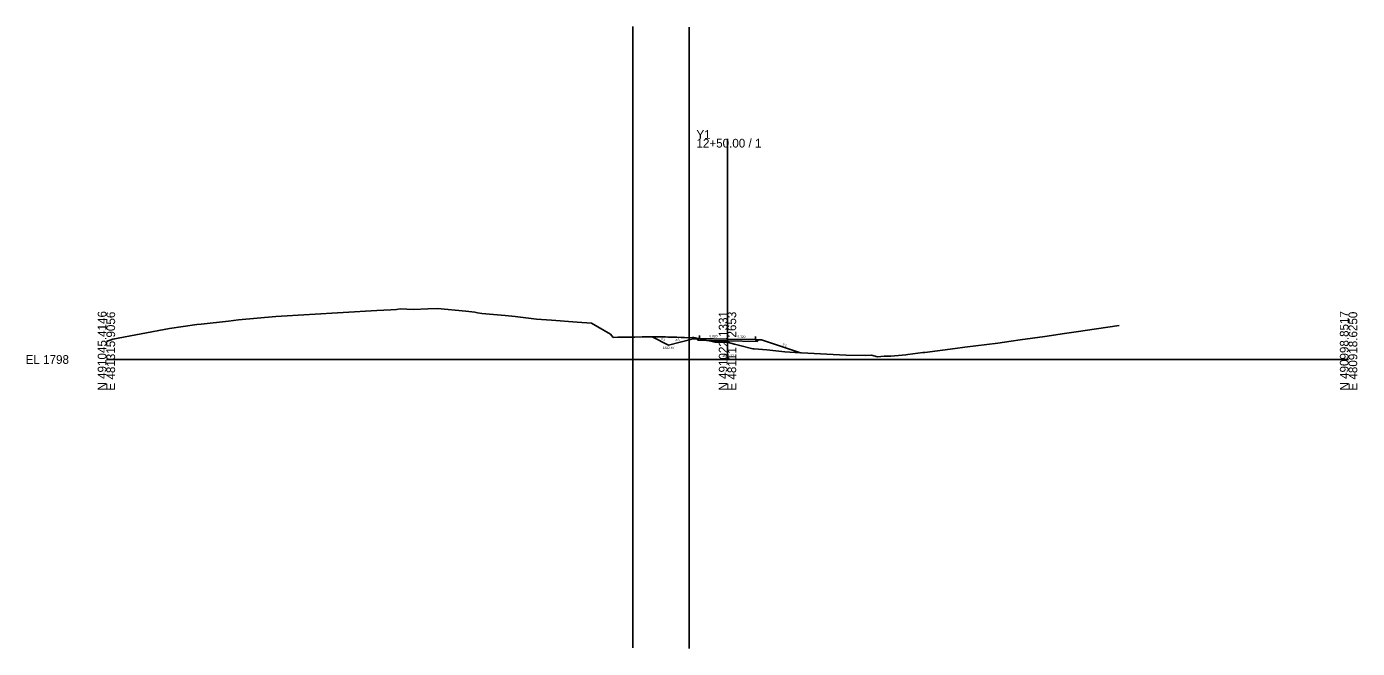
# Model space of a CAD drawing. Extents: x -26 to 403, y -10 to 6561.
# Drawn here: x -25.7 to 402.8, y 2407 to 2607.2 of the extents above; entities that cross this region are included whole.
import ezdxf

# ---------------------------------------------------------------- set-up
doc = ezdxf.new("R2010")
doc.units = 0
for name, color, linetype in [('Exist Cross Section Cell', 7, 'Continuous'), ('Exist XS Center Line Elevation Label', 7, 'Continuous'), ('Exist XS Ground Line', 7, 'Continuous'), ('Prop Road Sect_ Boring - Header (ID Tx)', 7, 'Continuous'), ('Prop Road Sect_ Material - Tx (Composite Desc)', 7, 'Continuous'), ('Prop XS Ditch Slope Text', 7, 'Continuous'), ('Prop XS Ditch Standard Text', 7, 'Continuous'), ('Prop XS EOT Tick Mark', 7, 'Continuous'), ('Prop XS Finish Grade', 7, 'Continuous'), ('Prop XS Finish Grade Earthwork', 7, 'Continuous'), ('Prop XS Finish Grade Pavement', 7, 'Continuous'), ('Prop XS Pvmt Edge Slope', 7, 'Continuous'), ('Prop XS SE Text', 7, 'Continuous'), ('Prop XS Side Slope Text', 7, 'Continuous'), ('Prop XS Subgrade Earthwork', 7, 'Continuous'), ('Scratch_Level_1', 7, 'Continuous')]:
    doc.layers.add(name, color=color, linetype=linetype)

msp = doc.modelspace()

# ---------------------------------------------------------------- linework, layer by layer
at = {"layer": 'Exist Cross Section Cell'}
for p, q in [((200, 2500), (200, 2571.04)), ((0, 2500), (200, 2500)), ((200, 2500), (400, 2500))]:
    msp.add_line(p, q, dxfattribs=at)
at = {"layer": 'Exist XS Ground Line'}
msp.add_lwpolyline([(0, 2505.84), (2.02, 2506.57), (20.27, 2509.97), (29.12, 2511.22), (30.53, 2511.41), (39.34, 2512.36), (42.55, 2512.72), (54.59, 2513.85), (87.06, 2515.79), (91.56, 2516.04), (93.38, 2516.14), (94.55, 2516.29), (98.94, 2516.1), (103.51, 2516.32), (106.6, 2516.41), (115.75, 2515.57), (118.65, 2515.21), (119.53, 2515.04), (120.93, 2514.85), (128.44, 2514.13), (131.66, 2513.85), (138.55, 2512.98), (143.38, 2512.66), (151.62, 2512.06), (156.21, 2511.71), (162.28, 2508.11), (163.23, 2507.13), (164.7, 2507.18), (165.48, 2507.18), (168.52, 2507.16), (169.54, 2507.16), (170.2, 2507.19), (172.5, 2507.26), (174.08, 2507.28), (175.15, 2507.28), (177.74, 2507.28), (178.75, 2507.28), (179.54, 2507.26), (180.04, 2507.25), (180.84, 2507.23), (182.54, 2507.2), (183.68, 2507.16), (185.05, 2507.12), (186.13, 2507.08), (187.66, 2507.01), (187.86, 2507.03), (188.71, 2507.04), (189.13, 2507.04), (193.16, 2506.19), (194.16, 2505.98), (194.68, 2505.88), (195.94, 2505.59), (198.56, 2505.57), (199.95, 2505.59), (202.22, 2504.92), (203.93, 2504.47), (208.19, 2503.49), (208.55, 2503.47), (212.63, 2503.13), (218.5, 2502.44), (220.07, 2502.39), (221.81, 2502.23), (236.05, 2501.52), (238.26, 2501.44), (244.53, 2501.33), (246.34, 2501.37), (248.35, 2500.81), (250.46, 2501.07), (252.62, 2501.12), (256.27, 2501.36), (257.38, 2501.52), (258.05, 2501.63), (262.89, 2502.22), (263.5, 2502.25), (273.34, 2503.57), (276.48, 2503.96), (287.1, 2505.31), (291.33, 2505.86), (294.26, 2506.3), (302.24, 2507.44), (308.55, 2508.33), (312.31, 2508.91), (318.81, 2509.88), (326.11, 2510.95)], dxfattribs=at)
at = {"layer": 'Prop Road Sect_ Boring - Header (ID Tx)'}
for points in [[(190.47, 2506.22), (189.98, 2506.71), (191, 2506.75)], [(210.06, 2506.35), (209.55, 2505.84), (209, 2506.39)]]:
    msp.add_lwpolyline(points, close=True, dxfattribs=at)
at = {"layer": 'Prop Road Sect_ Material - Tx (Composite Desc)'}
for points in [[(189, 2506.67), (189.98, 2506.71), (190.47, 2506.22), (193.28, 2506.16), (193.16, 2506.19), (189.13, 2507.04), (188.71, 2507.04), (187.86, 2507.03), (187.66, 2507.01), (186.13, 2507.08), (185.05, 2507.12), (183.68, 2507.16), (182.54, 2507.2), (180.84, 2507.23), (180.04, 2507.25), (179.54, 2507.26), (178.75, 2507.28), (177.74, 2507.28), (175.78, 2507.28), (181, 2504.67)], [(199.99, 2506.03), (209.55, 2505.84), (210.06, 2506.35), (211, 2506.31), (223.5, 2502.14), (221.81, 2502.23), (220.07, 2502.39), (218.5, 2502.44), (212.63, 2503.13), (208.55, 2503.47), (208.19, 2503.49), (203.93, 2504.47), (202.22, 2504.92), (199.95, 2505.59), (198.56, 2505.57), (195.94, 2505.59), (194.68, 2505.88), (194.16, 2505.98), (193.28, 2506.16)]]:
    msp.add_lwpolyline(points, close=True, dxfattribs=at)
at = {"layer": 'Prop XS EOT Tick Mark'}
for p, q in [((191, 2506.75), (191, 2507.75)), ((209, 2506.39), (209, 2507.39))]:
    msp.add_line(p, q, dxfattribs=at)
at = {"layer": 'Prop XS Finish Grade'}
for p, q in [((191, 2506.75), (189.98, 2506.71)), ((209, 2506.39), (210.06, 2506.35))]:
    msp.add_line(p, q, dxfattribs=at)
at = {"layer": 'Prop XS Finish Grade Earthwork'}
for p, q in [((181, 2504.67), (175.78, 2507.28)), ((189, 2506.67), (181, 2504.67)), ((189, 2506.67), (189.98, 2506.71)), ((210.06, 2506.35), (211, 2506.31)), ((211, 2506.31), (223.5, 2502.14))]:
    msp.add_line(p, q, dxfattribs=at)
at = {"layer": 'Prop XS Finish Grade Pavement'}
for p, q in [((191, 2506.75), (200, 2506.57)), ((200, 2506.57), (209, 2506.39))]:
    msp.add_line(p, q, dxfattribs=at)
at = {"layer": 'Prop XS Pvmt Edge Slope'}
for p, q in [((191, 2506.75), (190.47, 2506.22)), ((209, 2506.39), (209.55, 2505.84))]:
    msp.add_line(p, q, dxfattribs=at)
at = {"layer": 'Prop XS Subgrade Earthwork'}
for p, q in [((190.47, 2506.22), (189.98, 2506.71)), ((190.47, 2506.22), (199.99, 2506.03)), ((199.99, 2506.03), (209.55, 2505.84)), ((210.06, 2506.35), (209.55, 2505.84))]:
    msp.add_line(p, q, dxfattribs=at)
at = {"layer": 'Scratch_Level_1'}
for p, q in [((169.54, 2607.16), (169.54, 2407.16)), ((187.66, 2607.01), (187.66, 2407.01))]:
    msp.add_line(p, q, dxfattribs=at)

# ---------------------------------------------------------------- texts
at = {"layer": 'Exist Cross Section Cell'}
for s, p in [('Y1', (190, 2571.04)), ('12+50.00 / 1', (190, 2568.24)), ('EL 1798', (-26, 2498.6))]:
    msp.add_text(s, height=2.8, dxfattribs=at).set_placement(p)
for s, p in [('N 491045.4146', (0, 2490)), ('E 481315.9056', (2.8, 2490)), ('N 491022.1331', (200, 2490)), ('E 481117.2653', (202.8, 2490)), ('N 490998.8517', (400, 2490)), ('E 480918.6250', (402.8, 2490))]:
    msp.add_text(s, height=2.8, rotation=90, dxfattribs=at).set_placement(p)
at = {"layer": 'Exist XS Center Line Elevation Label'}
msp.add_text('1803.57', height=0.75, dxfattribs=at).set_placement((198.31, 2500.82))
at = {"layer": 'Prop XS Ditch Slope Text'}
msp.add_text('4:1', height=0.75, rotation=14.0362, dxfattribs=at).set_placement((183.33, 2505.82))
at = {"layer": 'Prop XS Ditch Standard Text'}
msp.add_text('1802.67', height=0.75, dxfattribs=at).set_placement((179.18, 2503.42))
at = {"layer": 'Prop XS SE Text'}
for p in [(194.17, 2507.19), (203.17, 2507.01)]:
    msp.add_text('0.020', height=0.75, rotation=358.8542, dxfattribs=at).set_placement(p)
at = {"layer": 'Prop XS Side Slope Text'}
for s, rotation, p in [('2:1', 333.4349, (178.52, 2506.59)), ('3:1', 341.5651, (217.6, 2504.54))]:
    msp.add_text(s, height=0.75, rotation=rotation, dxfattribs=at).set_placement(p)

doc.saveas('drawing.dxf')
